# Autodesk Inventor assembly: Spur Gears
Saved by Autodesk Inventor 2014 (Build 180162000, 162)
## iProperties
Created: 2010-12
Part Number: Spur Gears
Document SubType Name: Assembly
Designer: Thom Tremblay
Categories: <?xml version="1.0" encoding="UTF-16"?> <MemberInstance><Categories><FamilyTemplate/><ParamToTemplateMap><ParamToTemplate><ParamToTemplate CategoryParameter="//
ClientObjectVersion: 1
Author: Thom Tremblay
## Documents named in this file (2)
- C:\Inventor 2014 Essentials\Assemblies\Chapter 08\c08-01\Design Accelerator\Spur Gears2.iam
- C:\Inventor 2014 Essentials\Assemblies\Chapter 08\c08-01\Design Accelerator\Spur Gear22.ipt
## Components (1 placed, 1 different names)
1. Spur Gear2:1
